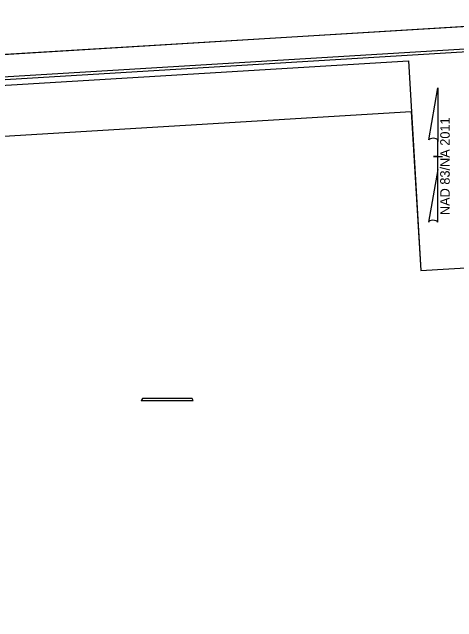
# Model space of a CAD drawing. Extents: x 2110128 to 2112690, y 669500 to 671339.
# Drawn here: x 2111836 to 2112232, y 670290 to 670834 of the extents above; entities that cross this region are included whole.
import ezdxf

# ---------------------------------------------------------------- set-up
doc = ezdxf.new("R2010")
doc.units = 0
for name, color, linetype in [('Default Symbol Cogo Number', 7, 'Continuous'), ('Exist Other Culture Sign Text', 7, 'Continuous'), ('Exist Roads Curbs', 7, 'Continuous'), ('Exist Roads Curbs Text', 7, 'Continuous'), ('Exist Roads EOP Other Text', 7, 'Continuous'), ('Exist Utilities TV Test Hole SUE LOS A Text', 7, 'Continuous'), ('Exist Utilities Water Fire Hydrant CELL', 7, 'Continuous'), ('Exist Utilities Water Test Hole SUE LOS A Text', 7, 'Continuous')]:
    doc.layers.add(name, color=color, linetype=linetype)

msp = doc.modelspace()

# ---------------------------------------------------------------- linework, layer by layer
at = {"layer": 'Default Symbol Cogo Number'}
for p, q in [((2111950.98, 670487.19), (2111951.85, 670489.19)), ((2111951.85, 670489.19), (2111950.98, 670487.19)), ((2111996.37, 670489.37), (2111951.85, 670489.19)), ((2111996.37, 670489.37), (2111951.85, 670489.19)), ((2111997.15, 670487.38), (2111996.37, 670489.37)), ((2111997.15, 670487.38), (2111996.37, 670489.37)), ((2111997.15, 670487.38), (2111950.98, 670487.19)), ((2111950.98, 670487.19), (2111997.15, 670487.38))]:
    msp.add_line(p, q, dxfattribs=at)
at = {"layer": 'Exist Other Culture Sign Text'}
for p, q in [((2112207.11, 670719.99), (2112215.33, 670766.33)), ((2112215.38, 670766.33), (2112215.33, 670766.33)), ((2112215.38, 670766.33), (2112215.33, 670766.33)), ((2112215.38, 670766.33), (2112215.36, 670718.53)), ((2112215.35, 670693.73), (2112215.36, 670719.93)), ((2112215.36, 670718.53), (2112215.36, 670719.88)), ((2112211.35, 670705.33), (2112211.3, 670705.33)), ((2112214.9, 670705.33), (2112211.35, 670705.33)), ((2112211.4, 670705.33), (2112219.4, 670705.33)), ((2112215.35, 670693.73), (2112206.98, 670646.49)), ((2112215.38, 670646.68), (2112215.35, 670693.73))]:
    msp.add_line(p, q, dxfattribs=at)
for centre, start_param, end_param in [((2112211.24, 670719.49), 0.216388, 2.908219), ((2112211.21, 670646.32), 0.201328, 3.141593)]:
    msp.add_ellipse(centre, major_axis=(4.23, -0.03), ratio=0.461098, start_param=start_param, end_param=end_param, dxfattribs=at)
at = {"layer": 'Exist Roads Curbs'}
msp.add_line((2112453.62, 670833.96), (2110773.2, 670732.11), dxfattribs=at)
at = {"layer": 'Exist Roads Curbs Text'}
msp.add_lwpolyline([(2112438.01, 670810.47), (2110940.76, 670719.73), (2111004.28, 669671.65), (2112501.53, 669762.39)], close=True, dxfattribs=at)
at = {"layer": 'Exist Roads EOP Other Text'}
msp.add_lwpolyline([(2110851.21, 669659.87), (2112514.16, 669760.65), (2112450.34, 670813.72), (2110787.39, 670712.94)], close=True, dxfattribs=at)
at = {"layer": 'Exist Utilities TV Test Hole SUE LOS A Text'}
msp.add_lwpolyline([(2111022.58, 670196.24), (2110993.69, 670672.84), (2112191.44, 670745.43), (2112200.05, 670603.34), (2112399.74, 670615.44), (2112420.01, 670280.93)], close=True, dxfattribs=at)
at = {"layer": 'Exist Utilities Water Fire Hydrant CELL'}
msp.add_lwpolyline([(2110944.98, 670715.17), (2112189.1, 670790.57), (2112200.05, 670603.34), (2112399.74, 670615.44), (2112418.35, 670308.36), (2112421.12, 670262.68), (2110980.52, 670175.37)], close=True, dxfattribs=at)
at = {"layer": 'Exist Utilities Water Test Hole SUE LOS A Text'}
msp.add_lwpolyline([(2110839.44, 669639.12), (2112519.86, 669740.96), (2112453.62, 670833.96), (2110773.2, 670732.11)], close=True, dxfattribs=at)

# ---------------------------------------------------------------- texts
at = {"layer": 'Exist Other Culture Sign Text'}
msp.add_text('NAD 83/NA 2011', height=8.5, rotation=89.9761, dxfattribs=at).set_placement((2112225.85, 670652.9))

doc.saveas('drawing.dxf')
